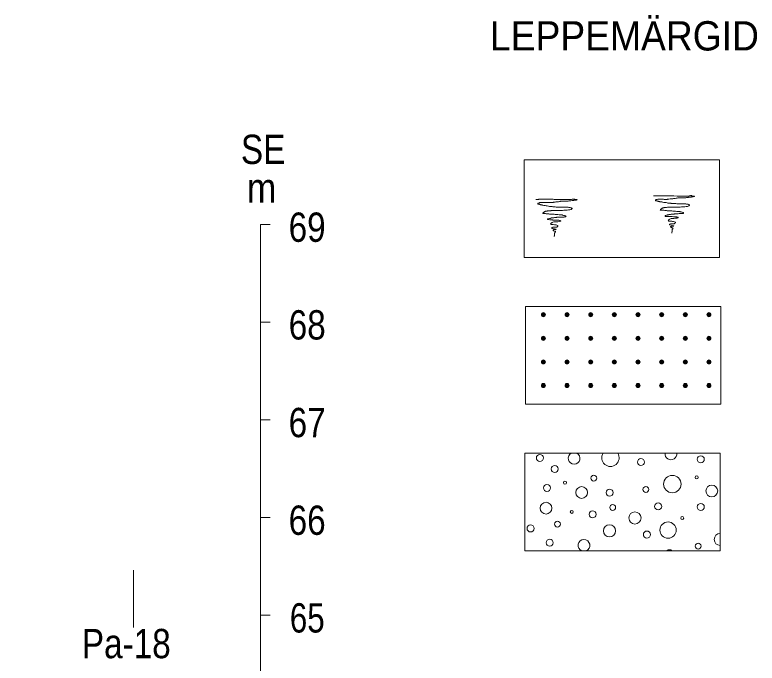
# Model space of a CAD drawing. Extents: x 640121 to 640955, y 6441885 to 6442246.
# Drawn here: x 640439.9 to 640515.9, y 6441983.5 to 6442049.9 of the extents above; entities that cross this region are included whole.
import ezdxf
from ezdxf.enums import TextEntityAlignment as Align

# ---------------------------------------------------------------- set-up
doc = ezdxf.new("R2010")
doc.units = 0
doc.header["$LTSCALE"] = 1.2
for name, color, linetype, lineweight in [('30', 7, 'Continuous', 13), ('32', 7, 'Continuous', 13), ('35', 7, 'Continuous', 35), ('50', 7, 'Continuous', 13)]:
    doc.layers.add(name, color=color, linetype=linetype, lineweight=lineweight)

msp = doc.modelspace()

# ---------------------------------------------------------------- hatches: boundary and pattern name
at = {"layer": '50'}
for points in [[(640494.192, 6442019.195, 1), (640493.772, 6442019.195, 1)], [(640496.612, 6442019.195, 1), (640496.192, 6442019.195, 1)], [(640499.032, 6442019.195, 1), (640498.612, 6442019.195, 1)], [(640501.452, 6442019.195, 1), (640501.032, 6442019.195, 1)], [(640503.872, 6442019.195, 1), (640503.452, 6442019.195, 1)], [(640506.292, 6442019.195, 1), (640505.872, 6442019.195, 1)], [(640508.712, 6442019.195, 1), (640508.292, 6442019.195, 1)], [(640511.132, 6442019.195, 1), (640510.712, 6442019.195, 1)], [(640494.192, 6442016.775, 1), (640493.772, 6442016.775, 1)], [(640496.612, 6442016.775, 1), (640496.192, 6442016.775, 1)], [(640499.032, 6442016.775, 1), (640498.612, 6442016.775, 1)], [(640501.452, 6442016.775, 1), (640501.032, 6442016.775, 1)], [(640503.872, 6442016.775, 1), (640503.452, 6442016.775, 1)], [(640506.292, 6442016.775, 1), (640505.872, 6442016.775, 1)], [(640508.712, 6442016.775, 1), (640508.292, 6442016.775, 1)], [(640511.132, 6442016.775, 1), (640510.712, 6442016.775, 1)], [(640494.192, 6442014.355, 1), (640493.772, 6442014.355, 1)], [(640496.612, 6442014.355, 1), (640496.192, 6442014.355, 1)], [(640499.032, 6442014.355, 1), (640498.612, 6442014.355, 1)], [(640501.452, 6442014.355, 1), (640501.032, 6442014.355, 1)], [(640503.872, 6442014.355, 1), (640503.452, 6442014.355, 1)], [(640506.292, 6442014.355, 1), (640505.872, 6442014.355, 1)], [(640508.712, 6442014.355, 1), (640508.292, 6442014.355, 1)], [(640511.132, 6442014.355, 1), (640510.712, 6442014.355, 1)], [(640494.192, 6442011.935, 1), (640493.772, 6442011.935, 1)], [(640496.612, 6442011.935, 1), (640496.192, 6442011.935, 1)], [(640499.032, 6442011.935, 1), (640498.612, 6442011.935, 1)], [(640501.452, 6442011.935, 1), (640501.032, 6442011.935, 1)], [(640503.872, 6442011.935, 1), (640503.452, 6442011.935, 1)], [(640506.292, 6442011.935, 1), (640505.872, 6442011.935, 1)], [(640508.712, 6442011.935, 1), (640508.292, 6442011.935, 1)], [(640511.132, 6442011.935, 1), (640510.712, 6442011.935, 1)]]:
    msp.add_hatch(color=256, dxfattribs=at).paths.add_polyline_path(points)

# ---------------------------------------------------------------- linework, layer by layer
at = {"layer": '30'}
for p, q in [((640465.01, 6442028.41), (640466.01, 6442028.41)), ((640465.01, 6442018.41), (640466.01, 6442018.41)), ((640465.01, 6442008.41), (640466.01, 6442008.41)), ((640465.01, 6441998.41), (640466.01, 6441998.41)), ((640465.01, 6441988.41), (640466.01, 6441988.41))]:
    msp.add_line(p, q, dxfattribs=at)
msp.add_lwpolyline([(640132.29, 6441898.41), (640465.01, 6441898.41), (640465.01, 6442028.41)], dxfattribs=at)
at = {"layer": '35', "lineweight": 13}
msp.add_line((640452.01, 6441987.17), (640452.01, 6441993.04), dxfattribs=at)
at = {"layer": '50'}
for points in [[(640492, 6442035.04), (640512, 6442035.04), (640512, 6442025.04), (640492, 6442025.04)], [(640492.13, 6442020.03), (640512.13, 6442020.03), (640512.13, 6442010.03), (640492.13, 6442010.03)], [(640492.07, 6442005.02), (640512.07, 6442005.02), (640512.07, 6441995.02), (640492.07, 6441995.02)]]:
    msp.add_lwpolyline(points, close=True, dxfattribs=at)
for points in [[(640493.21, 6442031), (640493.27, 6442031), (640493.38, 6442031), (640493.49, 6442031), (640493.51, 6442031.02), (640493.62, 6442031.02), (640493.78, 6442031.02), (640494.1, 6442031.02), (640494.28, 6442031.02), (640494.32, 6442031.02), (640494.35, 6442031.02), (640494.43, 6442031.02), (640494.51, 6442031.02), (640494.62, 6442031.02), (640494.7, 6442031.02), (640494.76, 6442031.02), (640494.85, 6442031.02), (640494.92, 6442031.02), (640494.99, 6442031.02), (640495.07, 6442031), (640495.12, 6442031), (640495.19, 6442031), (640495.29, 6442031), (640495.63, 6442030.99), (640495.94, 6442030.98), (640496.03, 6442030.98), (640496.09, 6442030.98), (640496.13, 6442030.98), (640496.18, 6442030.98), (640496.25, 6442030.98), (640496.35, 6442030.99), (640496.39, 6442030.99), (640496.43, 6442030.99), (640496.45, 6442030.99), (640496.49, 6442030.99), (640496.56, 6442030.98), (640496.6, 6442030.98), (640496.65, 6442030.98), (640496.74, 6442030.99), (640496.8, 6442030.99), (640496.87, 6442031), (640496.91, 6442031.02), (640496.98, 6442031.02), (640497.02, 6442031.03), (640497.07, 6442031.03), (640497.11, 6442031.03), (640497.15, 6442031.02), (640497.19, 6442031), (640497.23, 6442030.99), (640497.27, 6442030.99)], [(640497.27, 6442030.99), (640497.32, 6442030.98), (640497.35, 6442030.98), (640497.4, 6442030.98), (640497.43, 6442030.96), (640497.4, 6442030.94), (640497.41, 6442030.96), (640497.38, 6442030.94), (640497.33, 6442030.93), (640497.27, 6442030.92), (640497.23, 6442030.92), (640497.19, 6442030.92), (640497.15, 6442030.91), (640497.11, 6442030.91), (640497.09, 6442030.88), (640497.03, 6442030.88), (640496.96, 6442030.87), (640496.92, 6442030.87), (640496.8, 6442030.86), (640496.75, 6442030.85), (640496.72, 6442030.85), (640496.67, 6442030.84), (640496.62, 6442030.84), (640496.59, 6442030.84), (640496.53, 6442030.82), (640496.49, 6442030.82), (640496.38, 6442030.82), (640496.32, 6442030.82), (640496.25, 6442030.82), (640496.17, 6442030.82), (640496.11, 6442030.81), (640496.06, 6442030.81), (640496, 6442030.8), (640495.94, 6442030.8), (640495.77, 6442030.8), (640495.73, 6442030.8), (640495.7, 6442030.79), (640495.63, 6442030.78), (640495.53, 6442030.76), (640495.45, 6442030.75), (640495.39, 6442030.75), (640495.3, 6442030.74), (640495.24, 6442030.74), (640495.19, 6442030.72), (640495.13, 6442030.72), (640495.11, 6442030.7), (640495.07, 6442030.7), (640495.01, 6442030.7), (640494.97, 6442030.69), (640494.93, 6442030.69), (640494.8, 6442030.68), (640494.75, 6442030.68)], [(640505.25, 6442031.35), (640505.31, 6442031.35), (640505.42, 6442031.35), (640505.52, 6442031.35), (640505.55, 6442031.36), (640505.66, 6442031.36), (640505.81, 6442031.36), (640506.14, 6442031.36), (640506.32, 6442031.36), (640506.35, 6442031.36), (640506.39, 6442031.36), (640506.46, 6442031.36), (640506.54, 6442031.36), (640506.65, 6442031.36), (640506.74, 6442031.36), (640506.8, 6442031.36), (640506.88, 6442031.36), (640506.95, 6442031.36), (640507.02, 6442031.36), (640507.11, 6442031.35), (640507.16, 6442031.35), (640507.23, 6442031.35), (640507.32, 6442031.35), (640507.66, 6442031.34), (640507.97, 6442031.33), (640508.07, 6442031.33), (640508.13, 6442031.33), (640508.16, 6442031.33), (640508.21, 6442031.33), (640508.28, 6442031.33), (640508.38, 6442031.34), (640508.43, 6442031.34), (640508.46, 6442031.34), (640508.49, 6442031.34), (640508.52, 6442031.34), (640508.6, 6442031.33), (640508.63, 6442031.33), (640508.68, 6442031.33), (640508.78, 6442031.34), (640508.84, 6442031.34), (640508.91, 6442031.35), (640508.94, 6442031.36), (640509.02, 6442031.36), (640509.05, 6442031.38), (640509.1, 6442031.38), (640509.15, 6442031.38), (640509.18, 6442031.36), (640509.22, 6442031.35), (640509.27, 6442031.34), (640509.3, 6442031.34)], [(640506.78, 6442031.03), (640506.75, 6442031.02), (640506.69, 6442031.02), (640506.65, 6442031), (640506.62, 6442031), (640506.58, 6442031), (640506.53, 6442031), (640506.48, 6442031), (640506.44, 6442031), (640506.36, 6442031), (640506.33, 6442031), (640506.27, 6442031.02), (640506.23, 6442031.02), (640506.2, 6442031.02), (640506.16, 6442031.02), (640506.11, 6442031.02), (640506.06, 6442031.02), (640505.99, 6442031.02), (640505.96, 6442031.02), (640505.92, 6442031.02), (640505.86, 6442031.02), (640505.82, 6442031.02), (640505.78, 6442031.02), (640505.74, 6442031.02), (640505.69, 6442031.02), (640505.64, 6442031), (640505.61, 6442030.98), (640505.56, 6442030.98), (640505.52, 6442030.97), (640505.5, 6442030.96), (640505.48, 6442030.94), (640505.45, 6442030.92), (640505.44, 6442030.88), (640505.45, 6442030.85), (640505.55, 6442030.84), (640505.61, 6442030.84), (640505.64, 6442030.81), (640505.69, 6442030.81), (640505.73, 6442030.8), (640505.75, 6442030.79), (640505.81, 6442030.79), (640505.86, 6442030.78), (640505.9, 6442030.76), (640505.97, 6442030.74), (640506.04, 6442030.73), (640506.11, 6442030.73), (640506.16, 6442030.72), (640506.21, 6442030.7), (640506.29, 6442030.69), (640506.4, 6442030.68)], [(640509.3, 6442031.34), (640509.35, 6442031.33), (640509.39, 6442031.33), (640509.44, 6442031.33), (640509.46, 6442031.3), (640509.44, 6442031.29), (640509.45, 6442031.3), (640509.41, 6442031.29), (640509.36, 6442031.28), (640509.3, 6442031.27), (640509.27, 6442031.27), (640509.22, 6442031.27), (640509.18, 6442031.26), (640509.15, 6442031.26), (640509.12, 6442031.23), (640509.06, 6442031.23), (640508.99, 6442031.22), (640508.96, 6442031.22), (640508.84, 6442031.21), (640508.79, 6442031.2), (640508.75, 6442031.2), (640508.7, 6442031.18), (640508.66, 6442031.18), (640508.62, 6442031.18), (640508.56, 6442031.17), (640508.52, 6442031.17), (640508.42, 6442031.17), (640508.36, 6442031.17), (640508.28, 6442031.17), (640508.2, 6442031.17), (640508.14, 6442031.16), (640508.09, 6442031.16), (640508.03, 6442031.15), (640507.97, 6442031.15), (640507.8, 6442031.15), (640507.77, 6442031.15), (640507.73, 6442031.14), (640507.66, 6442031.12), (640507.56, 6442031.11), (640507.48, 6442031.1), (640507.42, 6442031.1), (640507.34, 6442031.09), (640507.28, 6442031.09), (640507.23, 6442031.06), (640507.17, 6442031.06), (640507.14, 6442031.05), (640507.11, 6442031.05), (640507.05, 6442031.05), (640507, 6442031.04), (640506.96, 6442031.04), (640506.83, 6442031.03), (640506.78, 6442031.03)], [(640494.75, 6442030.68), (640494.71, 6442030.67), (640494.65, 6442030.67), (640494.62, 6442030.66), (640494.58, 6442030.66), (640494.55, 6442030.66), (640494.5, 6442030.66), (640494.45, 6442030.66), (640494.4, 6442030.66), (640494.33, 6442030.66), (640494.29, 6442030.66), (640494.23, 6442030.67), (640494.2, 6442030.67), (640494.16, 6442030.67), (640494.13, 6442030.67), (640494.08, 6442030.67), (640494.03, 6442030.67), (640493.96, 6442030.67), (640493.92, 6442030.67), (640493.89, 6442030.67), (640493.83, 6442030.67), (640493.79, 6442030.67), (640493.74, 6442030.67), (640493.71, 6442030.67), (640493.66, 6442030.67), (640493.61, 6442030.66), (640493.57, 6442030.63), (640493.53, 6442030.63), (640493.49, 6442030.62), (640493.47, 6442030.61), (640493.44, 6442030.6), (640493.42, 6442030.57), (640493.41, 6442030.54), (640493.42, 6442030.5), (640493.51, 6442030.49), (640493.57, 6442030.49), (640493.61, 6442030.46), (640493.66, 6442030.46), (640493.69, 6442030.45), (640493.72, 6442030.44), (640493.78, 6442030.44), (640493.83, 6442030.43), (640493.86, 6442030.42), (640493.93, 6442030.39), (640494.01, 6442030.38), (640494.08, 6442030.38), (640494.13, 6442030.37), (640494.17, 6442030.36), (640494.26, 6442030.34), (640494.37, 6442030.33)], [(640494.37, 6442030.33), (640494.51, 6442030.31), (640494.61, 6442030.28), (640494.67, 6442030.27), (640494.76, 6442030.26), (640494.86, 6442030.26), (640494.93, 6442030.25), (640494.99, 6442030.25), (640495.04, 6442030.22), (640495.12, 6442030.22), (640495.18, 6442030.22), (640495.27, 6442030.21), (640495.35, 6442030.21), (640495.42, 6442030.21), (640495.52, 6442030.21), (640495.6, 6442030.2), (640495.66, 6442030.2), (640495.7, 6442030.2), (640495.77, 6442030.2), (640495.84, 6442030.2), (640495.93, 6442030.2), (640496.02, 6442030.2), (640496.11, 6442030.2), (640496.17, 6442030.2), (640496.25, 6442030.2), (640496.29, 6442030.2), (640496.35, 6442030.2), (640496.41, 6442030.2), (640496.47, 6442030.19), (640496.53, 6442030.19), (640496.57, 6442030.18), (640496.71, 6442030.16), (640496.77, 6442030.14), (640496.83, 6442030.12), (640496.87, 6442030.1), (640496.91, 6442030.09), (640496.91, 6442030.06), (640496.9, 6442030.02), (640496.87, 6442030.01), (640496.85, 6442030), (640496.83, 6442029.97), (640496.78, 6442029.96), (640496.69, 6442029.94), (640496.55, 6442029.92), (640496.42, 6442029.9), (640496.35, 6442029.89), (640496.25, 6442029.89), (640496.17, 6442029.88), (640496.07, 6442029.88), (640495.94, 6442029.86), (640495.75, 6442029.86), (640495.58, 6442029.86)], [(640507.61, 6442030.21), (640507.53, 6442030.21), (640507.46, 6442030.21), (640507.37, 6442030.21), (640507.31, 6442030.21), (640507.25, 6442030.21), (640507.17, 6442030.21), (640507.08, 6442030.2), (640506.9, 6442030.2), (640506.82, 6442030.2), (640506.77, 6442030.19), (640506.69, 6442030.19), (640506.57, 6442030.16), (640506.44, 6442030.16), (640506.39, 6442030.15), (640506.33, 6442030.15), (640506.3, 6442030.14), (640506.27, 6442030.13), (640506.23, 6442030.13), (640506.2, 6442030.12), (640506.16, 6442030.1), (640506.14, 6442030.08), (640506.08, 6442030.04), (640506.04, 6442030.02), (640506.03, 6442030), (640505.99, 6442029.98), (640505.98, 6442029.96), (640505.96, 6442029.94), (640505.94, 6442029.91), (640505.97, 6442029.9), (640506, 6442029.9), (640506.06, 6442029.9), (640506.11, 6442029.9), (640506.22, 6442029.89), (640506.3, 6442029.88), (640506.4, 6442029.86), (640506.52, 6442029.85), (640506.58, 6442029.85), (640506.64, 6442029.83), (640506.7, 6442029.83), (640506.87, 6442029.83), (640507, 6442029.83), (640507.11, 6442029.82), (640507.22, 6442029.8), (640507.36, 6442029.79), (640507.5, 6442029.79), (640507.62, 6442029.76), (640507.71, 6442029.76), (640507.8, 6442029.76), (640507.89, 6442029.74)], [(640506.4, 6442030.68), (640506.54, 6442030.66), (640506.64, 6442030.63), (640506.7, 6442030.62), (640506.8, 6442030.61), (640506.89, 6442030.61), (640506.96, 6442030.6), (640507.02, 6442030.6), (640507.07, 6442030.57), (640507.16, 6442030.57), (640507.22, 6442030.57), (640507.3, 6442030.56), (640507.38, 6442030.56), (640507.46, 6442030.56), (640507.55, 6442030.56), (640507.64, 6442030.55), (640507.7, 6442030.55), (640507.73, 6442030.55), (640507.8, 6442030.55), (640507.88, 6442030.55), (640507.96, 6442030.55), (640508.06, 6442030.55), (640508.14, 6442030.55), (640508.2, 6442030.55), (640508.28, 6442030.55), (640508.32, 6442030.55), (640508.38, 6442030.55), (640508.44, 6442030.55), (640508.5, 6442030.54), (640508.56, 6442030.54), (640508.61, 6442030.52), (640508.74, 6442030.51), (640508.8, 6442030.49), (640508.86, 6442030.46), (640508.91, 6442030.45), (640508.94, 6442030.44), (640508.94, 6442030.4), (640508.93, 6442030.37), (640508.91, 6442030.36), (640508.88, 6442030.34), (640508.86, 6442030.32), (640508.81, 6442030.31), (640508.73, 6442030.28), (640508.58, 6442030.27), (640508.45, 6442030.25), (640508.38, 6442030.24), (640508.28, 6442030.24), (640508.2, 6442030.22), (640508.1, 6442030.22), (640507.97, 6442030.21), (640507.78, 6442030.21), (640507.61, 6442030.21)], [(640495.58, 6442029.86), (640495.49, 6442029.86), (640495.42, 6442029.86), (640495.34, 6442029.86), (640495.28, 6442029.86), (640495.22, 6442029.86), (640495.13, 6442029.86), (640495.05, 6442029.85), (640494.87, 6442029.85), (640494.79, 6442029.85), (640494.74, 6442029.84), (640494.65, 6442029.84), (640494.53, 6442029.82), (640494.4, 6442029.82), (640494.35, 6442029.8), (640494.29, 6442029.8), (640494.27, 6442029.79), (640494.23, 6442029.78), (640494.2, 6442029.78), (640494.16, 6442029.77), (640494.13, 6442029.76), (640494.1, 6442029.73), (640494.04, 6442029.7), (640494.01, 6442029.67), (640493.99, 6442029.65), (640493.96, 6442029.64), (640493.95, 6442029.61), (640493.92, 6442029.59), (640493.91, 6442029.56), (640493.93, 6442029.55), (640493.97, 6442029.55), (640494.03, 6442029.55), (640494.08, 6442029.55), (640494.19, 6442029.54), (640494.27, 6442029.53), (640494.37, 6442029.52), (640494.49, 6442029.5), (640494.55, 6442029.5), (640494.61, 6442029.48), (640494.67, 6442029.48), (640494.83, 6442029.48), (640494.97, 6442029.48), (640495.07, 6442029.47), (640495.18, 6442029.46), (640495.33, 6442029.44), (640495.47, 6442029.44), (640495.59, 6442029.41), (640495.67, 6442029.41), (640495.77, 6442029.41), (640495.85, 6442029.4)], [(640495.85, 6442029.4), (640495.9, 6442029.4), (640495.95, 6442029.38), (640496.03, 6442029.36), (640496.11, 6442029.35), (640496.15, 6442029.32), (640496.2, 6442029.31), (640496.26, 6442029.3), (640496.29, 6442029.29), (640496.3, 6442029.24), (640496.27, 6442029.23), (640496.25, 6442029.22), (640496.21, 6442029.2), (640496.09, 6442029.19), (640496.03, 6442029.19), (640496, 6442029.19), (640495.93, 6442029.19), (640495.84, 6442029.19), (640495.76, 6442029.18), (640495.71, 6442029.18), (640495.66, 6442029.18), (640495.53, 6442029.18), (640495.46, 6442029.16), (640495.42, 6442029.16), (640495.36, 6442029.16), (640495.33, 6442029.14), (640495.27, 6442029.14), (640495.18, 6442029.14), (640495.11, 6442029.13), (640495.03, 6442029.12), (640494.97, 6442029.11), (640494.93, 6442029.11), (640494.88, 6442029.11), (640494.85, 6442029.1), (640494.79, 6442029.1), (640494.77, 6442029.07), (640494.71, 6442029.06), (640494.69, 6442029.05), (640494.65, 6442029.05), (640494.61, 6442029.04), (640494.55, 6442029.02), (640494.49, 6442029.01), (640494.44, 6442028.99), (640494.41, 6442028.96), (640494.41, 6442028.92), (640494.45, 6442028.92), (640494.52, 6442028.92), (640494.62, 6442028.9), (640494.7, 6442028.9), (640494.75, 6442028.9), (640494.85, 6442028.89), (640494.91, 6442028.89)], [(640507.89, 6442029.74), (640507.94, 6442029.74), (640507.98, 6442029.73), (640508.07, 6442029.71), (640508.14, 6442029.7), (640508.19, 6442029.67), (640508.24, 6442029.66), (640508.3, 6442029.65), (640508.32, 6442029.64), (640508.33, 6442029.59), (640508.31, 6442029.58), (640508.28, 6442029.56), (640508.25, 6442029.55), (640508.13, 6442029.54), (640508.07, 6442029.54), (640508.03, 6442029.54), (640507.96, 6442029.54), (640507.88, 6442029.54), (640507.79, 6442029.53), (640507.74, 6442029.53), (640507.7, 6442029.53), (640507.56, 6442029.53), (640507.49, 6442029.5), (640507.46, 6442029.5), (640507.4, 6442029.5), (640507.36, 6442029.49), (640507.3, 6442029.49), (640507.22, 6442029.49), (640507.14, 6442029.48), (640507.06, 6442029.47), (640507, 6442029.46), (640506.96, 6442029.46), (640506.92, 6442029.46), (640506.88, 6442029.44), (640506.82, 6442029.44), (640506.81, 6442029.42), (640506.75, 6442029.41), (640506.72, 6442029.4), (640506.69, 6442029.4), (640506.64, 6442029.38), (640506.58, 6442029.37), (640506.52, 6442029.36), (640506.47, 6442029.34), (640506.45, 6442029.31), (640506.45, 6442029.26), (640506.48, 6442029.26), (640506.56, 6442029.26), (640506.65, 6442029.25), (640506.74, 6442029.25), (640506.78, 6442029.25), (640506.88, 6442029.24), (640506.94, 6442029.24)], [(640494.91, 6442028.89), (640494.93, 6442028.88), (640494.97, 6442028.88), (640495.03, 6442028.88), (640495.1, 6442028.88), (640495.13, 6442028.88), (640495.24, 6442028.87), (640495.33, 6442028.87), (640495.36, 6442028.87), (640495.41, 6442028.87), (640495.45, 6442028.87), (640495.51, 6442028.87), (640495.57, 6442028.86), (640495.61, 6442028.83), (640495.66, 6442028.82), (640495.71, 6442028.81), (640495.75, 6442028.8), (640495.75, 6442028.75), (640495.63, 6442028.72), (640495.47, 6442028.71), (640495.41, 6442028.71), (640495.3, 6442028.7), (640495.24, 6442028.7), (640495.17, 6442028.7), (640495.1, 6442028.69), (640495.03, 6442028.69), (640494.95, 6442028.66), (640494.87, 6442028.63), (640494.85, 6442028.6), (640494.8, 6442028.58), (640494.77, 6442028.56), (640494.75, 6442028.53), (640494.74, 6442028.5), (640494.71, 6442028.46), (640494.74, 6442028.45), (640494.79, 6442028.44), (640494.86, 6442028.41), (640494.99, 6442028.41), (640495.1, 6442028.4), (640495.16, 6442028.39), (640495.21, 6442028.38), (640495.28, 6442028.38), (640495.36, 6442028.36), (640495.46, 6442028.33), (640495.46, 6442028.28), (640495.45, 6442028.24), (640495.43, 6442028.22), (640495.36, 6442028.16), (640495.33, 6442028.15), (640495.27, 6442028.15), (640495.18, 6442028.15), (640495.1, 6442028.15), (640495.03, 6442028.15), (640494.94, 6442028.15), (640494.86, 6442028.12), (640494.85, 6442028.09), (640494.83, 6442028.06), (640494.85, 6442028.04), (640494.88, 6442028.03), (640495, 6442027.99), (640495.09, 6442027.98), (640495.13, 6442027.97), (640495.19, 6442027.96), (640495.25, 6442027.94), (640495.29, 6442027.92), (640495.27, 6442027.91), (640495.21, 6442027.91), (640495.13, 6442027.9), (640495.04, 6442027.88), (640495, 6442027.88), (640494.97, 6442027.87), (640494.97, 6442027.82), (640494.99, 6442027.8), (640495.01, 6442027.79), (640495.05, 6442027.76), (640495.1, 6442027.75), (640495.16, 6442027.74), (640495.21, 6442027.73), (640495.22, 6442027.68), (640495.19, 6442027.66), (640495.18, 6442027.62), (640495.16, 6442027.58), (640495.13, 6442027.56), (640495.13, 6442027.51), (640495.13, 6442027.46), (640495.13, 6442027.43), (640495.12, 6442027.39), (640495.12, 6442027.34), (640495.11, 6442027.32), (640495.1, 6442027.27), (640495.09, 6442027.24), (640495.09, 6442027.19), (640495.09, 6442027.18), (640495.09, 6442027.21)], [(640506.94, 6442029.24), (640506.96, 6442029.23), (640507, 6442029.23), (640507.06, 6442029.23), (640507.13, 6442029.23), (640507.17, 6442029.23), (640507.28, 6442029.22), (640507.36, 6442029.22), (640507.4, 6442029.22), (640507.44, 6442029.22), (640507.48, 6442029.22), (640507.54, 6442029.22), (640507.6, 6442029.2), (640507.65, 6442029.18), (640507.7, 6442029.17), (640507.74, 6442029.16), (640507.78, 6442029.14), (640507.78, 6442029.1), (640507.66, 6442029.07), (640507.5, 6442029.06), (640507.44, 6442029.06), (640507.34, 6442029.05), (640507.28, 6442029.05), (640507.2, 6442029.05), (640507.13, 6442029.04), (640507.06, 6442029.04), (640506.99, 6442029.01), (640506.9, 6442028.98), (640506.88, 6442028.95), (640506.83, 6442028.93), (640506.81, 6442028.9), (640506.78, 6442028.88), (640506.77, 6442028.84), (640506.75, 6442028.81), (640506.77, 6442028.8), (640506.82, 6442028.78), (640506.89, 6442028.76), (640507.02, 6442028.76), (640507.13, 6442028.75), (640507.19, 6442028.74), (640507.24, 6442028.72), (640507.31, 6442028.72), (640507.4, 6442028.71), (640507.49, 6442028.68), (640507.49, 6442028.63), (640507.48, 6442028.59), (640507.47, 6442028.57), (640507.4, 6442028.51), (640507.36, 6442028.5), (640507.3, 6442028.5), (640507.22, 6442028.5), (640507.13, 6442028.5), (640507.06, 6442028.5), (640506.98, 6442028.5), (640506.89, 6442028.47), (640506.88, 6442028.44), (640506.87, 6442028.41), (640506.88, 6442028.39), (640506.92, 6442028.38), (640507.04, 6442028.34), (640507.12, 6442028.33), (640507.17, 6442028.32), (640507.23, 6442028.3), (640507.29, 6442028.29), (640507.32, 6442028.27), (640507.3, 6442028.26), (640507.24, 6442028.26), (640507.17, 6442028.24), (640507.07, 6442028.23), (640507.04, 6442028.23), (640507, 6442028.22), (640507, 6442028.17), (640507.02, 6442028.15), (640507.05, 6442028.14), (640507.08, 6442028.11), (640507.13, 6442028.1), (640507.19, 6442028.09), (640507.24, 6442028.08), (640507.25, 6442028.03), (640507.23, 6442028), (640507.22, 6442027.97), (640507.19, 6442027.93), (640507.17, 6442027.91), (640507.17, 6442027.86), (640507.17, 6442027.81), (640507.17, 6442027.78), (640507.16, 6442027.74), (640507.16, 6442027.69), (640507.14, 6442027.67), (640507.13, 6442027.62), (640507.12, 6442027.58), (640507.12, 6442027.54), (640507.12, 6442027.52), (640507.12, 6442027.56)]]:
    msp.add_lwpolyline(points, dxfattribs=at)
for centre, radius in [((640493.982, 6442019.195), 0.21), ((640496.402, 6442019.195), 0.21), ((640498.822, 6442019.195), 0.21), ((640501.242, 6442019.195), 0.21), ((640503.662, 6442019.195), 0.21), ((640506.082, 6442019.195), 0.21), ((640508.502, 6442019.195), 0.21), ((640510.922, 6442019.195), 0.21), ((640493.982, 6442016.775), 0.21), ((640496.402, 6442016.775), 0.21), ((640498.822, 6442016.775), 0.21), ((640501.242, 6442016.775), 0.21), ((640503.662, 6442016.775), 0.21), ((640506.082, 6442016.775), 0.21), ((640508.502, 6442016.775), 0.21), ((640510.922, 6442016.775), 0.21), ((640493.982, 6442014.355), 0.21), ((640496.402, 6442014.355), 0.21), ((640498.822, 6442014.355), 0.21), ((640501.242, 6442014.355), 0.21), ((640503.662, 6442014.355), 0.21), ((640506.082, 6442014.355), 0.21), ((640508.502, 6442014.355), 0.21), ((640510.922, 6442014.355), 0.21), ((640493.982, 6442011.935), 0.21), ((640496.402, 6442011.935), 0.21), ((640498.822, 6442011.935), 0.21), ((640501.242, 6442011.935), 0.21), ((640503.662, 6442011.935), 0.21), ((640506.082, 6442011.935), 0.21), ((640508.502, 6442011.935), 0.21), ((640510.922, 6442011.935), 0.21), ((640493.618, 6442004.524), 0.36), ((640503.963, 6442004.1), 0.36), ((640510.087, 6442004.386), 0.36), ((640495.136, 6442003.392), 0.36), ((640496.189, 6442001.995), 0.15), ((640499.135, 6442002.46), 0.3), ((640507.18, 6442001.846), 0.893), ((640509.666, 6442002.538), 0.15), ((640494.344, 6442001.454), 0.36), ((640497.893, 6442000.984), 0.6), ((640500.755, 6442000.971), 0.36), ((640504.47, 6442001.296), 0.3), ((640511.217, 6442001.14), 0.6), ((640494.248, 6441999.384), 0.6), ((640505.725, 6441999.564), 0.36), ((640510.087, 6441999.507), 0.36), ((640496.885, 6441998.994), 0.15), ((640499.014, 6441998.747), 0.36), ((640501.073, 6441999.459), 0.3), ((640503.35, 6441998.378), 0.624), ((640508.193, 6441998.373), 0.15), ((640492.663, 6441997.306), 0.36), ((640495.412, 6441997.752), 0.3), ((640500.748, 6441997.058), 0.624), ((640506.741, 6441997.136), 0.835), ((640504.573, 6441996.683), 0.36), ((640494.627, 6441995.845), 0.36), ((640509.822, 6441995.496), 0.3)]:
    msp.add_circle(centre, radius, dxfattribs=at)
for centre, radius, start, end in [((640497.119, 6442004.479), 0.6, 116.62565, 63.37435), ((640500.837, 6442004.535), 0.889, 147.31794, 32.68206), ((640507.029, 6442004.947), 0.6, 173.45672, 6.54328), ((640512.087, 6441996.18), 0.624, 91.92421, 268.07579), ((640498.127, 6441995.577), 0.6, 290.60215, 249.39785), ((640506.88, 6441994.769), 0.36, 43.29551, 136.70449)]:
    msp.add_arc(centre, radius, start, end, dxfattribs=at)

# ---------------------------------------------------------------- texts
at = {"layer": '30'}
for s, width, p in [('SE', 0.85, (640465.29, 6442034.62)), ('m', 0.9, (640465.13, 6442030.67)), ('69', 0.85, (640469.795, 6442026.65)), ('68', 0.85, (640469.8, 6442016.65)), ('67', 0.85, (640469.795, 6442006.65)), ('66', 0.85, (640469.795, 6441996.65)), ('65', 0.8, (640469.805, 6441986.65))]:
    msp.add_text(s, height=3, dxfattribs=dict(at, width=width)).set_placement(p, align=Align.CENTER)
at = {"layer": '32', "width": 0.85}
msp.add_text('Pa-18', height=3, dxfattribs=at).set_placement((640451.28, 6441984.02), align=Align.CENTER)
at = {"layer": '50', "width": 0.95}
msp.add_text('LEPPEMÄRGID', height=3, dxfattribs=at).set_placement((640502.275, 6442046.24), align=Align.CENTER)

doc.saveas('drawing.dxf')
